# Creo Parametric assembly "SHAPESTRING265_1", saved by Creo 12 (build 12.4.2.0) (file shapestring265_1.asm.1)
Units: Custom; MM, KILOGRAM, SECS

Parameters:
  PTC_WM_ITERATION = "0"
  PTC_WM_VERSION = "-.0"
  PTC_WM_LIFECYCLE_STATE = "In Work"
  PTC_WM_LIFECYCLE = "MO_CADDocument"
  PTC_WM_CREATED_BY = "Maximilian Roepper (Z0017RMS: MO)"
  PTC_WM_CREATED_ON = "18-Sep-26 11:36:42 AM"
  PTC_WM_MODIFIED_BY = "Maximilian Roepper (Z0017RMS: MO)"
  PTC_WM_MODIFIED_ON = "18-Sep-26 11:36:46 AM"
  PDMLINKNUMBER = "PDM000071454761"
  PTC_WM_NUMBER = "PDM000071454761"

Other parameters: WEIGHT, WEIGHT_FACTOR, WEIGHT_ADD, MC_ERRORS, SUPPLIER

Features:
  1. coordinate system
  2. imported feature
  3. component "SHAPESTRING004_1"
  4. component "SHAPESTRING263_1"
  5. component "SHAPESTRING264_1"

Other named items: DRW_VIEW_ORG, ROUGH-GROB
